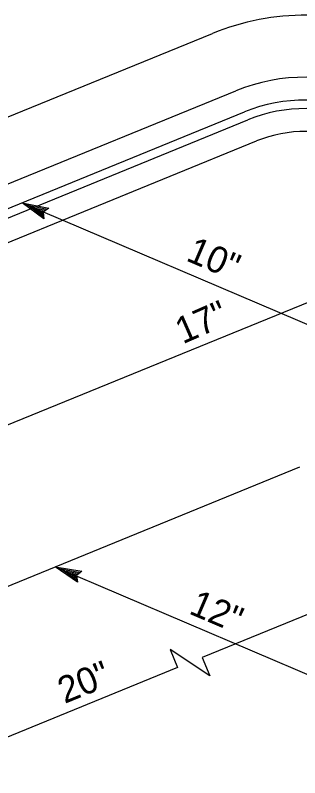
# Model space of a CAD drawing. Extents: x -121933 to -117742, y -103160 to -100084.
# Drawn here: x -120930 to -120865.6, y -101483 to -101310.1 of the extents above; entities that cross this region are included whole.
import ezdxf

# ---------------------------------------------------------------- set-up
doc = ezdxf.new("R2010")
doc.units = 0
for name, color, linetype in [('G-MARK', 7, 'Continuous'), ('G-TEXT', 7, 'Continuous'), ('Misc CnstDet(22)', 7, 'Continuous')]:
    doc.layers.add(name, color=color, linetype=linetype)

msp = doc.modelspace()

# ---------------------------------------------------------------- linework, layer by layer
at = {"layer": 'G-MARK'}
for p, q in [((-120805.41, -101351.36), (-120947.94, -101409.62)), ((-120928.46, -101352.6), (-120846.6, -101387.59)), ((-120920.98, -101435.17), (-120840.87, -101469.41))]:
    msp.add_line(p, q, dxfattribs=at)
msp.add_lwpolyline([(-120840.87, -101436.65), (-120887.68, -101455.78), (-120885.99, -101459.9), (-120894.96, -101453.95), (-120893.28, -101458.07), (-120954.37, -101483.05)], dxfattribs=at)
at = {"layer": 'G-TEXT'}
for p, q in [((-120923.55, -101356.29), (-120928.46, -101352.6)), ((-120928.46, -101352.6), (-120928.46, -101352.6)), ((-120928.46, -101352.6), (-120922.45, -101353.86)), ((-120923.6, -101355.88), (-120927.21, -101353.17)), ((-120927.2, -101353.17), (-120922.81, -101354.09)), ((-120923.66, -101355.45), (-120925.95, -101353.74)), ((-120925.95, -101353.74), (-120923.12, -101354.33)), ((-120923.68, -101355.07), (-120924.69, -101354.31)), ((-120924.69, -101354.31), (-120923.48, -101354.56)), ((-120922.45, -101353.86), (-120923.73, -101354.74)), ((-120922.45, -101353.86), (-120922.45, -101353.86)), ((-120923.73, -101354.74), (-120923.55, -101356.29)), ((-120923.55, -101356.29), (-120923.55, -101356.29)), ((-120915.94, -101438.69), (-120920.98, -101435.17)), ((-120920.98, -101435.17), (-120920.98, -101435.17)), ((-120920.98, -101435.17), (-120914.93, -101436.22)), ((-120916.01, -101438.28), (-120919.71, -101435.69)), ((-120919.7, -101435.69), (-120915.28, -101436.46)), ((-120916.09, -101437.86), (-120918.43, -101436.22)), ((-120918.43, -101436.22), (-120915.58, -101436.71)), ((-120916.12, -101437.47), (-120917.15, -101436.75)), ((-120917.15, -101436.75), (-120915.93, -101436.96)), ((-120914.93, -101436.22), (-120916.17, -101437.14)), ((-120916.17, -101437.14), (-120915.94, -101438.69)), ((-120914.93, -101436.22), (-120914.93, -101436.22)), ((-120915.94, -101438.69), (-120915.94, -101438.69))]:
    msp.add_line(p, q, dxfattribs=at)
at = {"layer": 'Misc CnstDet(22)'}
for p, q in [((-121015.38, -101367.35), (-120885.39, -101314.22)), ((-121002.65, -101377.33), (-120880.08, -101327.22)), ((-121001.77, -101382.57), (-120878.12, -101332.02)), ((-120999.27, -101383.64), (-120877.38, -101333.81)), ((-120992.57, -101386.5), (-120875.42, -101338.61)), ((-120954.37, -101448.82), (-120865.61, -101412.53))]:
    msp.add_line(p, q, dxfattribs=at)
for radius in [55.52, 41.47, 36.29, 34.35, 29.17]:
    msp.add_arc((-120864.39, -101365.61), radius, 66.8572, 112.2327, dxfattribs=at)

# ---------------------------------------------------------------- texts
for s, rotation, p in [('10"', 336.8572, (-120891.61, -101365.64)), ('17"', 23.6156, (-120892.11, -101384.75)), ('12"', 336.8572, (-120890.96, -101445.72)), ('20"', 22.2327, (-120918.86, -101466.31))]:
    msp.add_text(s, height=6, rotation=rotation, dxfattribs=at).set_placement(p)

doc.saveas('drawing.dxf')
